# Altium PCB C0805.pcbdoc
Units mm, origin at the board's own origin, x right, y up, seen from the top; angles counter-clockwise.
Board outline 16.63 x 14.51 mm, 2 copper layers (Top Layer, Bottom Layer); 1 components, 0 nets, 2 pads, 0 vias.
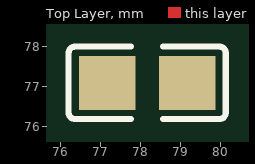
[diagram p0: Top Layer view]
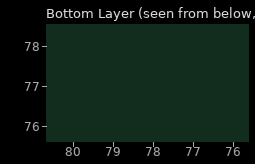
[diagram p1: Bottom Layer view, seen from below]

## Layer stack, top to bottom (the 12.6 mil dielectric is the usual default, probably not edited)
Top Layer: signal copper (thickness not stored)
Dielectric: dielectric 0.32, FR-4, Dk 4.8
Bottom Layer: signal copper (thickness not stored)

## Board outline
86.477,69.85 69.85,69.85 69.85,84.357 86.477,84.357

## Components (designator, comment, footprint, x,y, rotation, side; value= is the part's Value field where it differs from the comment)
? "C0805" C0805 78.164,77.104 r0 top

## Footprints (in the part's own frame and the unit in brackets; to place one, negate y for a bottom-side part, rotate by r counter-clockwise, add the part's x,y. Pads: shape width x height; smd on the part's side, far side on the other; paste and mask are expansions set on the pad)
C0805 [mm]
  rect 1.41x1.35 smd: 1(-1,0) 2(1,0)
  silkscreen extent -1.96,-0.9 1.96,0.9

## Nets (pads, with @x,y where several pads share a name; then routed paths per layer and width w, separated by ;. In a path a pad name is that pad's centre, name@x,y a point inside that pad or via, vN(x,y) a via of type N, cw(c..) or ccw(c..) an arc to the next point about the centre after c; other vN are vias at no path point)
pads on no net: ?.1 ?.2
